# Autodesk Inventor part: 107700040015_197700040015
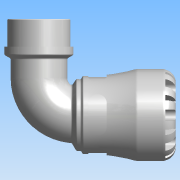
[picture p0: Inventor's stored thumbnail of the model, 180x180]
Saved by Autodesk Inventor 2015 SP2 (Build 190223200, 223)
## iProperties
Created: 2016-12
Part Number: 107700040015_197700040015
Material: PVC-Piping
Description: PLASSON 90° ELBOW WITH MALE INTEGRAL BRASS 40X1.1/2" SERIES 1
Document SubType Name: Modeling
Designer: KIM
Mass: 664.223 g
Surface Area: 733.008 cm^2
Volume: 474.445 cm^3
Density: 1.4 g/cm^3
Appearance: Smooth - White
Author: KIM
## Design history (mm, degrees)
derived "1077.ipt"
feature "Solid1::1077.ipt"
tag "TaggingFeature1"
body "Solid1"
other parameters: "d1" = 29.82, "d8" = 59.5, "d13" = 8, "d14" = 8, "d15" = 0, "d17" = 360 deg, "d19" = 8 deg, "d20" = 0.8, "d21" = 0.8, "d22" = 8 deg, "d24" = 0, "d26" = 360 deg, "d33" = 7, "d43" = 54.6, "d51" = 0.7, "d54" = 14, "d55" = 8.8, "d57" = 15.68, "d58" = 0, "d74" = 0, "d78" = 71, "d82" = 0.8, "d115" = 360 deg, "d207" = 90 deg, "d228" = 11.9, "d247" = 1.4, "d248" = 4.26, "d268" = 32.725, "d269" = 4.26, "d270" = 104, "d276" = 47.803, "d277" = 21, "d278" = 52.5833, "d279" = 73, "d280" = 27.3, "d281" = 7.17045, "d283" = 43.0227, "d286" = 0, "d287" = 0, "d288" = 33.4621, "d290" = 5.78865, "d292" = 30 deg, "d294" = 4.7803, "d296" = 30 deg, "l_" = 71, "A_" = 104, "A_1" = 73, "l_2" = 21, "R_" = 47.803, "d9" = 10, "d289" = 33.4621
